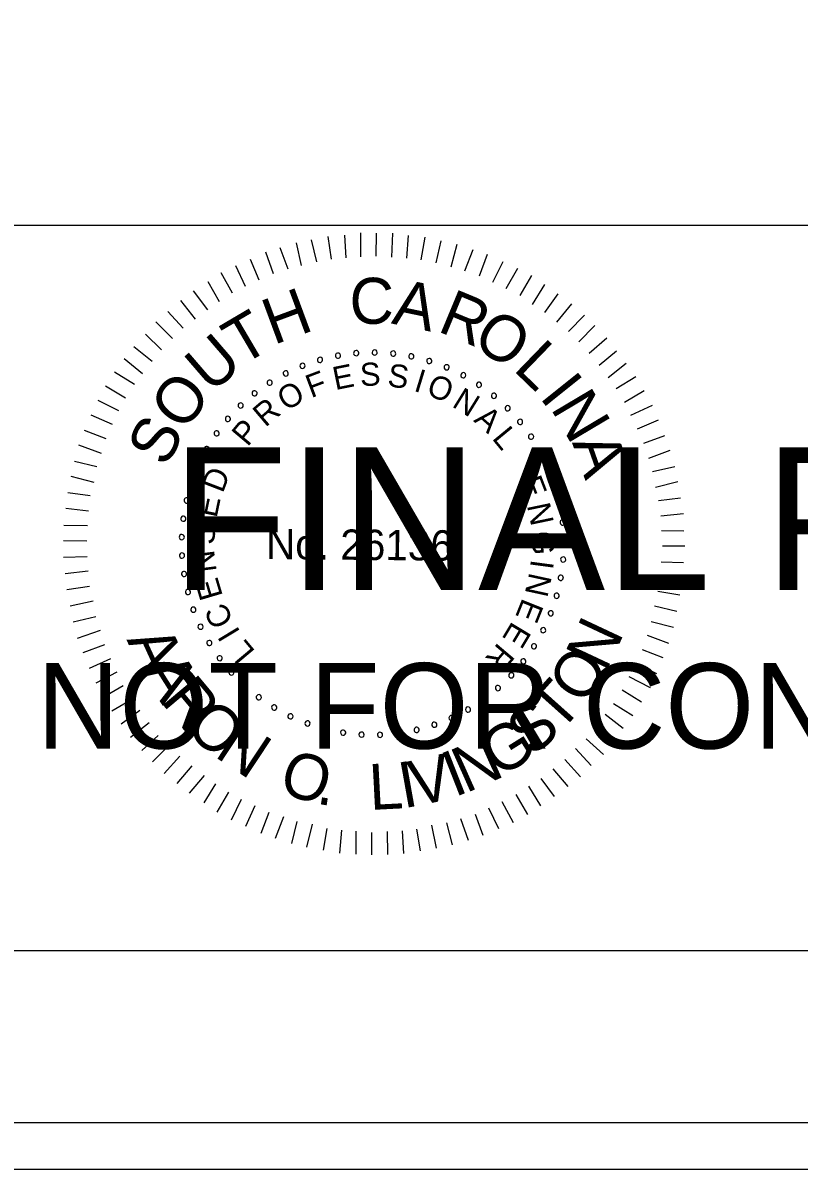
# Model space of a CAD drawing. Extents: x 967 to 1326, y 964 to 3144.
# Drawn here: x 1170.56 to 1189.3, y 1803.72 to 1831.36 of the extents above; entities that cross this region are included whole.
import ezdxf

# ---------------------------------------------------------------- set-up
doc = ezdxf.new("R2010")
doc.units = 0
for name, color, linetype in [('RD_XS_EwShp', 7, 'Continuous'), ('RD_XS_ExPaveRet', 7, 'Continuous'), ('RD_XS_TX_Elev_EX', 7, 'Continuous'), ('RD_XS_TX_Elev_PR', 7, 'Continuous'), ('RD_XS_TX_Station', 7, 'Continuous')]:
    doc.layers.add(name, color=color, linetype=linetype)

msp = doc.modelspace()

# ---------------------------------------------------------------- linework, layer by layer
at = {"layer": 'RD_XS_ExPaveRet'}
for points in [[(967.409, 1803.72), (1326.285, 1803.72), (1326.285, 2023.72), (967.409, 2023.72)], [(988.525, 1804.84), (1326.285, 1804.84), (1326.285, 2022.6), (988.525, 2022.6)]]:
    msp.add_lwpolyline(points, close=True, dxfattribs=at)
at = {"layer": 'RD_XS_TX_Elev_EX'}
for p, q in [((996.114, 1826.486), (1323.886, 1826.486)), ((1323.886, 1808.983), (996.114, 1808.983))]:
    msp.add_line(p, q, dxfattribs=at)
at = {"layer": 'RD_XS_TX_Elev_PR'}
for p, q in [((1178.01, 1825.663), (1177.93, 1826.209)), ((1178.364, 1825.699), (1178.33, 1826.244)), ((1178.717, 1825.719), (1178.722, 1826.295)), ((1179.093, 1825.739), (1179.098, 1826.292)), ((1179.469, 1825.713), (1179.489, 1826.288)), ((1179.829, 1825.687), (1179.872, 1826.231)), ((1180.174, 1825.646), (1180.271, 1826.19)), ((1176.964, 1825.419), (1176.769, 1825.935)), ((1177.287, 1825.508), (1177.169, 1826.054)), ((1177.657, 1825.597), (1177.53, 1826.128)), ((1180.535, 1825.573), (1180.662, 1826.102)), ((1180.902, 1825.478), (1181.045, 1826.022)), ((1181.231, 1825.384), (1181.428, 1825.896)), ((1176.264, 1825.156), (1176.053, 1825.657)), ((1176.61, 1825.306), (1176.423, 1825.83)), ((1181.584, 1825.265), (1181.78, 1825.786)), ((1181.905, 1825.109), (1182.154, 1825.606)), ((1175.624, 1824.846), (1175.352, 1825.332)), ((1175.933, 1825.005), (1175.699, 1825.506)), ((1182.226, 1824.953), (1182.506, 1825.45)), ((1175.308, 1824.634), (1175.036, 1825.12)), ((1182.562, 1824.789), (1182.85, 1825.27)), ((1175.03, 1824.445), (1174.681, 1824.9)), ((1182.86, 1824.572), (1183.163, 1825.053)), ((1183.158, 1824.378), (1183.484, 1824.828)), ((1174.729, 1824.217), (1174.372, 1824.665)), ((1183.447, 1824.145), (1183.811, 1824.587)), ((1174.435, 1823.997), (1174.062, 1824.399)), ((1183.729, 1823.92), (1184.116, 1824.316)), ((1174.172, 1823.753), (1173.776, 1824.148)), ((1183.98, 1823.672), (1184.368, 1824.061)), ((1173.909, 1823.479), (1173.52, 1823.858)), ((1184.232, 1823.394), (1184.657, 1823.767)), ((1173.684, 1823.197), (1173.242, 1823.546)), ((1184.475, 1823.108), (1184.892, 1823.45)), ((1173.451, 1822.9), (1173.009, 1823.256)), ((1184.687, 1822.807), (1185.128, 1823.156)), ((1173.257, 1822.64), (1172.776, 1822.936)), ((1173.039, 1822.312), (1172.559, 1822.6)), ((1184.885, 1822.544), (1185.355, 1822.832)), ((1185.081, 1822.213), (1185.56, 1822.493)), ((1172.883, 1822.006), (1172.379, 1822.256)), ((1185.24, 1821.904), (1185.756, 1822.145)), ((1172.727, 1821.677), (1172.215, 1821.904)), ((1185.399, 1821.573), (1185.907, 1821.791)), ((1172.571, 1821.333), (1172.051, 1821.53)), ((1185.549, 1821.226), (1186.057, 1821.414)), ((1172.461, 1820.974), (1171.91, 1821.178)), ((1185.669, 1820.865), (1186.185, 1821.06)), ((1172.351, 1820.652), (1171.807, 1820.787)), ((1185.759, 1820.541), (1186.297, 1820.667)), ((1172.286, 1820.276), (1171.727, 1820.419)), ((1185.832, 1820.165), (1186.371, 1820.298)), ((1172.191, 1819.955), (1171.647, 1820.029)), ((1185.906, 1819.842), (1186.436, 1819.906)), ((1172.15, 1819.587), (1171.598, 1819.653)), ((1185.964, 1819.473), (1186.51, 1819.53)), ((1172.124, 1819.234), (1171.548, 1819.239)), ((1185.977, 1819.12), (1186.514, 1819.115)), ((1172.105, 1818.866), (1171.545, 1818.871)), ((1185.997, 1818.751), (1186.542, 1818.747)), ((1172.118, 1818.482), (1171.542, 1818.471)), ((1185.971, 1818.368), (1186.508, 1818.348)), ((1172.138, 1818.136), (1171.585, 1818.072)), ((1185.952, 1818.022), (1186.497, 1817.949)), ((1172.173, 1817.768), (1171.627, 1817.688)), ((1185.888, 1817.655), (1186.417, 1817.566)), ((1172.262, 1817.414), (1171.701, 1817.296)), ((1185.808, 1817.302), (1186.345, 1817.175)), ((1172.321, 1817.037), (1171.774, 1816.911)), ((1185.729, 1816.926), (1186.265, 1816.792)), ((1172.425, 1816.707), (1171.871, 1816.519)), ((1185.634, 1816.597), (1186.146, 1816.401)), ((1172.53, 1816.36), (1172.007, 1816.173)), ((1185.508, 1816.253), (1186.013, 1816.057)), ((1172.681, 1816.029), (1172.165, 1815.788)), ((1172.831, 1815.705), (1172.323, 1815.441)), ((1185.352, 1815.924), (1185.857, 1815.675)), ((1185.188, 1815.603), (1185.7, 1815.33)), ((1172.982, 1815.374), (1172.497, 1815.094)), ((1185.024, 1815.274), (1185.498, 1814.987)), ((1173.194, 1815.042), (1172.709, 1814.762)), ((1184.822, 1814.946), (1185.288, 1814.658)), ((1173.384, 1814.78), (1172.936, 1814.453)), ((1184.62, 1814.687), (1185.055, 1814.353)), ((1173.612, 1814.478), (1173.164, 1814.129)), ((1184.403, 1814.389), (1184.814, 1814.033)), ((1173.832, 1814.177), (1173.437, 1813.812)), ((1184.155, 1814.092), (1184.574, 1813.72)), ((1174.091, 1813.945), (1173.689, 1813.541)), ((1183.899, 1813.864), (1184.28, 1813.454)), ((1174.35, 1813.674), (1173.97, 1813.263)), ((1183.644, 1813.597), (1184.024, 1813.18)), ((1174.64, 1813.442), (1174.275, 1813.022)), ((1174.937, 1813.209), (1174.58, 1812.782)), ((1183.358, 1813.37), (1183.715, 1812.944)), ((1175.212, 1813.014), (1174.932, 1812.549)), ((1182.764, 1812.952), (1183.059, 1812.482)), ((1183.065, 1813.141), (1183.384, 1812.709)), ((1175.525, 1812.812), (1175.245, 1812.331)), ((1175.83, 1812.633), (1175.588, 1812.136)), ((1182.463, 1812.755), (1182.743, 1812.269)), ((1176.159, 1812.477), (1175.94, 1811.98)), ((1181.8, 1812.431), (1182.041, 1811.93)), ((1182.124, 1812.581), (1182.396, 1812.08)), ((1176.503, 1812.321), (1176.307, 1811.816)), ((1176.855, 1812.211), (1176.651, 1811.69)), ((1177.177, 1812.1), (1177.05, 1811.572)), ((1180.791, 1812.07), (1180.926, 1811.54)), ((1181.122, 1812.175), (1181.31, 1811.652)), ((1181.476, 1812.28), (1181.664, 1811.771)), ((1177.545, 1812.036), (1177.409, 1811.484)), ((1177.897, 1811.933), (1177.808, 1811.412)), ((1178.25, 1811.892), (1178.207, 1811.34)), ((1178.603, 1811.866), (1178.598, 1811.313)), ((1178.978, 1811.84), (1178.974, 1811.295)), ((1179.355, 1811.86), (1179.365, 1811.307)), ((1179.715, 1811.88), (1179.749, 1811.327)), ((1180.061, 1811.915), (1180.149, 1811.393)), ((1180.423, 1812.012), (1180.541, 1811.458))]:
    msp.add_line(p, q, dxfattribs=at)
for centre, start, end in [((1178.168, 1823.337), 10.6038, 190.6038), ((1178.609, 1823.397), 5.0653, 185.0653), ((1178.609, 1823.397), 185.0653, 5.0653), ((1179.055, 1823.414), 359.5268, 179.5268), ((1179.055, 1823.414), 179.5268, 359.5268), ((1179.5, 1823.388), 353.9884, 173.9884), ((1177.312, 1823.091), 21.6807, 201.6807), ((1177.734, 1823.235), 16.1422, 196.1422), ((1177.734, 1823.235), 196.1422, 16.1422), ((1178.168, 1823.337), 190.6038, 10.6038), ((1179.5, 1823.388), 173.9884, 353.9884), ((1179.94, 1823.319), 168.4499, 348.4499), ((1179.94, 1823.319), 348.4499, 168.4499), ((1180.372, 1823.208), 162.9114, 342.9114), ((1180.372, 1823.208), 342.9114, 162.9114), ((1180.79, 1823.056), 337.373, 157.373), ((1176.906, 1822.908), 27.2191, 207.2191), ((1176.906, 1822.908), 207.2191, 27.2191), ((1177.312, 1823.091), 201.6807, 21.6807), ((1180.79, 1823.056), 157.373, 337.373), ((1181.193, 1822.864), 151.8345, 331.8345), ((1181.193, 1822.864), 331.8345, 151.8345), ((1176.52, 1822.686), 32.7576, 212.7576), ((1176.52, 1822.686), 212.7576, 32.7576), ((1181.574, 1822.634), 146.2961, 326.2961), ((1181.574, 1822.634), 326.2961, 146.2961), ((1176.156, 1822.428), 38.2961, 218.2961), ((1176.156, 1822.428), 218.2961, 38.2961), ((1181.932, 1822.368), 140.7576, 320.7576), ((1181.932, 1822.368), 320.7576, 140.7576), ((1175.82, 1822.135), 43.8345, 223.8345), ((1175.82, 1822.135), 223.8345, 43.8345), ((1182.263, 1822.069), 135.2191, 315.2191), ((1182.263, 1822.069), 315.2191, 135.2191), ((1175.513, 1821.812), 49.373, 229.373), ((1175.513, 1821.812), 229.373, 49.373), ((1182.563, 1821.74), 129.6807, 309.6807), ((1182.563, 1821.74), 309.6807, 129.6807), ((1175.239, 1821.461), 54.9114, 234.9114), ((1175.239, 1821.461), 234.9114, 54.9114), ((1182.83, 1821.383), 124.1422, 304.1422), ((1182.83, 1821.383), 304.1422, 124.1422), ((1175, 1821.085), 60.4499, 240.4499), ((1175, 1821.085), 240.4499, 60.4499), ((1183.061, 1821.002), 118.6038, 298.6038), ((1183.061, 1821.002), 298.6038, 118.6038), ((1174.798, 1820.687), 65.9884, 245.9884), ((1174.798, 1820.687), 245.9884, 65.9884), ((1183.255, 1820.601), 113.0653, 293.0653), ((1183.255, 1820.601), 293.0653, 113.0653), ((1174.636, 1820.272), 71.5268, 251.5268), ((1174.636, 1820.272), 251.5268, 71.5268), ((1183.408, 1820.182), 107.5268, 287.5268), ((1183.408, 1820.182), 287.5268, 107.5268), ((1174.514, 1819.843), 77.0653, 257.0653), ((1174.514, 1819.843), 257.0653, 77.0653), ((1183.521, 1819.751), 101.9884, 281.9884), ((1183.521, 1819.751), 281.9884, 101.9884), ((1174.435, 1819.405), 82.6038, 262.6038), ((1174.435, 1819.405), 262.6038, 82.6038), ((1183.592, 1819.311), 96.4499, 276.4499), ((1183.592, 1819.311), 276.4499, 96.4499), ((1174.398, 1818.961), 88.1422, 268.1422), ((1174.398, 1818.961), 268.1422, 88.1422), ((1183.619, 1818.866), 90.9114, 270.9114), ((1183.619, 1818.866), 270.9114, 90.9114), ((1174.404, 1818.515), 93.6807, 273.6807), ((1174.404, 1818.515), 273.6807, 93.6807), ((1183.604, 1818.421), 85.373, 265.373), ((1183.604, 1818.421), 265.373, 85.373), ((1174.453, 1818.072), 99.2191, 279.2191), ((1174.453, 1818.072), 279.2191, 99.2191), ((1183.546, 1817.979), 79.8345, 259.8345), ((1183.546, 1817.979), 259.8345, 79.8345), ((1174.545, 1817.636), 104.7576, 284.7576), ((1174.545, 1817.636), 284.7576, 104.7576), ((1183.445, 1817.545), 74.2961, 254.2961), ((1183.445, 1817.545), 254.2961, 74.2961), ((1174.678, 1817.211), 110.2961, 290.2961), ((1174.678, 1817.211), 290.2961, 110.2961), ((1183.303, 1817.122), 68.7576, 248.7576), ((1183.303, 1817.122), 248.7576, 68.7576), ((1174.852, 1816.8), 115.8345, 295.8345), ((1174.852, 1816.8), 295.8345, 115.8345), ((1183.121, 1816.716), 63.2191, 243.2191), ((1183.121, 1816.716), 243.2191, 63.2191), ((1175.065, 1816.409), 121.373, 301.373), ((1175.065, 1816.409), 301.373, 121.373), ((1182.9, 1816.328), 57.6807, 237.6807), ((1182.9, 1816.328), 237.6807, 57.6807), ((1175.314, 1816.039), 126.9114, 306.9114), ((1175.314, 1816.039), 306.9114, 126.9114), ((1182.643, 1815.964), 52.1422, 232.1422), ((1182.643, 1815.964), 232.1422, 52.1422), ((1175.598, 1815.696), 132.4499, 312.4499), ((1175.598, 1815.696), 312.4499, 132.4499), ((1182.353, 1815.627), 46.6038, 226.6038), ((1182.353, 1815.627), 226.6038, 46.6038), ((1175.914, 1815.381), 137.9884, 317.9884), ((1175.914, 1815.381), 317.9884, 137.9884), ((1182.03, 1815.319), 41.0653, 221.0653), ((1176.258, 1815.099), 143.5268, 323.5268), ((1176.258, 1815.099), 323.5268, 143.5268), ((1181.68, 1815.043), 35.5268, 215.5268), ((1182.03, 1815.319), 221.0653, 41.0653), ((1176.629, 1814.851), 149.0653, 329.0653), ((1176.629, 1814.851), 329.0653, 149.0653), ((1181.305, 1814.803), 29.9884, 209.9884), ((1181.305, 1814.803), 209.9884, 29.9884), ((1181.68, 1815.043), 215.5268, 35.5268), ((1177.021, 1814.639), 154.6038, 334.6038), ((1177.021, 1814.639), 334.6038, 154.6038), ((1180.908, 1814.6), 24.4499, 204.4499), ((1180.908, 1814.6), 204.4499, 24.4499), ((1177.432, 1814.467), 160.1422, 340.1422), ((1177.432, 1814.467), 340.1422, 160.1422), ((1177.858, 1814.335), 165.6807, 345.6807), ((1177.858, 1814.335), 345.6807, 165.6807), ((1178.294, 1814.245), 351.2191, 171.2191), ((1179.627, 1814.232), 7.8345, 187.8345), ((1180.065, 1814.313), 13.373, 193.373), ((1180.065, 1814.313), 193.373, 13.373), ((1180.494, 1814.436), 18.9114, 198.9114), ((1180.494, 1814.436), 198.9114, 18.9114), ((1178.294, 1814.245), 171.2191, 351.2191), ((1178.737, 1814.198), 356.7576, 176.7576), ((1178.737, 1814.198), 176.7576, 356.7576), ((1179.183, 1814.193), 2.2961, 182.2961), ((1179.183, 1814.193), 182.2961, 2.2961), ((1179.627, 1814.232), 187.8345, 7.8345)]:
    msp.add_arc(centre, 0.0627, start, end, dxfattribs=at)
at = {"layer": 'RD_XS_TX_Station'}
msp.add_lwpolyline([(967.409, 1803.72), (1326.285, 1803.72), (1326.285, 2023.72), (967.409, 2023.72)], close=True, dxfattribs=at)

# ---------------------------------------------------------------- texts
at = {"layer": 'RD_XS_EwShp'}
for s, height, p in [('FINAL PLANS', 3.4375, (1174.145, 1817.685)), ('NOT FOR CONSTRUCTION', 2.0625, (1170.901, 1813.86))]:
    msp.add_text(s, height=height, dxfattribs=at).set_placement(p)
at = {"layer": 'RD_XS_TX_Elev_PR'}
for s, height, rotation, p in [('C', 1.11, 359.5482, (1178.442, 1824.108)), ('A', 1.11, 348.1981, (1179.439, 1824.115)), ('H', 1.11, 20.3637, (1176.614, 1823.587)), ('R', 1.11, 337.4344, (1180.541, 1823.937)), ('T', 1.11, 30.4992, (1175.828, 1823.072)), ('O', 1.108, 326.5869, (1181.366, 1823.609)), ('U', 1.11, 40.8022, (1175.102, 1822.403)), ('L', 1.11, 315.9488, (1182.373, 1823.003)), ('E', 0.557, 11.4103, (1178.103, 1822.503)), ('S', 0.557, 2.208, (1178.709, 1822.601)), ('S', 0.557, 352.6608, (1179.346, 1822.599)), ('O', 1.11, 52.0267, (1174.435, 1821.474)), ('F', 0.557, 20.6127, (1177.52, 1822.309)), ('I', 0.557, 343.1136, (1179.975, 1822.491)), ('O', 0.557, 338.4392, (1180.274, 1822.401)), ('I', 1.11, 308.6613, (1183.011, 1822.338)), ('O', 0.557, 30.8477, (1176.917, 1821.987)), ('N', 0.557, 328.2042, (1180.896, 1822.12)), ('N', 1.11, 300.7037, (1183.285, 1822.075)), ('R', 0.557, 40.3949, (1176.415, 1821.594)), ('A', 0.557, 318.657, (1181.424, 1821.762)), ('S', 1.108, 63.2511, (1174.029, 1820.619)), ('P', 0.557, 49.9421, (1175.985, 1821.124)), ('L', 0.557, 309.4546, (1181.869, 1821.339)), ('A', 1.11, 289.4792, (1183.814, 1821.243)), ('D', 0.557, 69.0364, (1175.386, 1820.003)), ('E', 0.557, 291.049, (1182.53, 1820.307)), ('E', 0.557, 78.2388, (1175.238, 1819.407)), ('N', 0.557, 281.8466, (1182.728, 1819.726)), ('S', 0.557, 87.786, (1175.187, 1818.772)), ('No. 26136', 0.7311, 359.5268, (1176.429, 1818.43)), ('G', 0.557, 272.2995, (1182.833, 1819.097)), ('N', 0.557, 97.3332, (1175.242, 1818.137)), ('I', 0.557, 262.4084, (1182.83, 1818.437)), ('E', 0.557, 106.5355, (1175.394, 1817.541)), ('N', 0.557, 257.7339, (1182.789, 1818.127)), ('C', 0.557, 116.4266, (1175.661, 1816.938)), ('E', 0.557, 248.1867, (1182.628, 1817.511)), ('I', 0.557, 121.1011, (1175.823, 1816.67)), ('E', 0.557, 238.9844, (1182.378, 1816.949)), ('N', 1.105, 64.8922, (1184.632, 1815.684)), ('A', 1.105, 294.7297, (1173.062, 1816.486)), ('L', 0.557, 129.9595, (1176.187, 1816.204)), ('R', 0.557, 229.782, (1182.041, 1816.435)), ('O', 1.105, 56.2059, (1184.102, 1814.874)), ('A', 1.105, 302.2892, (1173.414, 1815.72)), ('R', 1.105, 309.8487, (1173.865, 1815.007)), ('T', 1.105, 48.2685, (1183.515, 1814.211)), ('O', 1.105, 317.7861, (1174.434, 1814.33)), ('S', 1.105, 40.3311, (1182.842, 1813.636)), ('N', 1.105, 326.4725, (1175.158, 1813.686)), ('G', 1.105, 32.0198, (1182.059, 1813.14)), ('N', 1.105, 24.0824, (1181.252, 1812.776)), ('O', 1.105, 342.3472, (1176.697, 1812.82)), ('V', 1.105, 12.7741, (1180.033, 1812.457)), ('I', 1.105, 21.4605, (1180.976, 1812.681)), ('L', 1.105, 2.9677, (1178.943, 1812.379)), ('I', 1.105, 10.1523, (1179.743, 1812.418)), ('.', 1.105, 351.0336, (1177.623, 1812.536))]:
    msp.add_text(s, height=height, rotation=rotation, dxfattribs=at).set_placement(p)

doc.saveas('drawing.dxf')
